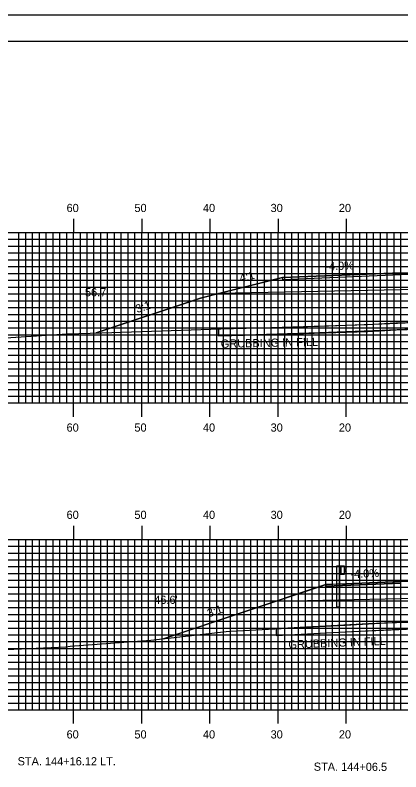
# Model space of a CAD drawing. Extents: x 1777138 to 1777481, y 442591 to 442811.
# Drawn here: x 1777235.2 to 1777291.8, y 442699.6 to 442810.5 of the extents above; entities that cross this region are included whole.
import ezdxf

# ---------------------------------------------------------------- set-up
doc = ezdxf.new("R2010")
doc.units = 0
for name, color, linetype in [('ANNOTATION', 7, 'Continuous'), ('BORDER', 7, 'Continuous'), ('BORING - NO REFUSAL', 7, 'Continuous'), ('D_Guardrail_Beam_Lt', 7, 'Continuous'), ('D_Roadway_Centerline', 7, 'Continuous'), ('D_Roadway_Edge_Shoulder', 7, 'Continuous'), ('D_Roadway_SlopeLines', 7, 'Continuous'), ('D_Roadway_SubGrade', 7, 'Continuous'), ('D_Text_Standard', 7, 'Continuous'), ('GRUBBING IN FILL', 7, 'Continuous'), ('H_V ANNOTATION', 7, 'Continuous'), ('MAJOR', 7, 'Continuous'), ('MINOR', 7, 'Continuous'), ('PLOT BOUNDARY', 7, 'Continuous'), ('S_Roadway_Centerline', 7, 'Continuous')]:
    doc.layers.add(name, color=color, linetype=linetype)

msp = doc.modelspace()

# ---------------------------------------------------------------- linework, layer by layer
at = {"layer": 'BORDER'}
msp.add_lwpolyline([(1777154.16, 442596.67), (1777474.16, 442596.67), (1777474.16, 442806.67), (1777154.16, 442806.67)], close=True, dxfattribs=at)
at = {"layer": 'D_Guardrail_Beam_Lt'}
for p, q in [((1777282.33, 442729.74), (1777282.33, 442723.74)), ((1777282.81, 442729.74), (1777282.33, 442729.74)), ((1777283.49, 442729.74), (1777282.81, 442729.74)), ((1777282.81, 442729.74), (1777282.81, 442728.57)), ((1777282.87, 442729.74), (1777282.87, 442728.57)), ((1777282.97, 442729.74), (1777282.97, 442728.57)), ((1777283.49, 442728.57), (1777283.49, 442729.74)), ((1777283.49, 442729.66), (1777283.57, 442729.64)), ((1777283.58, 442729.64), (1777283.73, 442729.54)), ((1777282.81, 442728.57), (1777283.49, 442728.57)), ((1777282.83, 442723.74), (1777282.83, 442728.57)), ((1777283.57, 442728.67), (1777283.49, 442728.66)), ((1777283.5, 442729.19), (1777283.5, 442729.12)), ((1777283.73, 442729.39), (1777283.53, 442729.26)), ((1777283.53, 442729.06), (1777283.73, 442728.92)), ((1777283.73, 442728.78), (1777283.58, 442728.68)), ((1777282.83, 442723.74), (1777282.33, 442723.74))]:
    msp.add_line(p, q, dxfattribs=at)
for centre, major_axis, start_param, end_param in [((1777283.56, 442729.6), (0.0417, 0), 0.959931, 1.376053), ((1777283.58, 442729.19), (-0.0789, 0), 5.323254, 6.283185), ((1777283.58, 442729.12), (-0.0789, 0), 6.283185, 7.243116), ((1777283.56, 442728.71), (0.0417, 0), 4.907132, 5.323254), ((1777283.68, 442729.46), (0.0877, 0), 5.323254, 7.243116), ((1777283.68, 442728.85), (0.0877, 0), 5.323254, 7.243116)]:
    msp.add_ellipse(centre, major_axis=major_axis, ratio=0.995501, start_param=start_param, end_param=end_param, dxfattribs=at)
at = {"layer": 'D_Roadway_Centerline'}
for points in [[(1777247.09, 442763.95), (1777262.4, 442769.05), (1777262.91, 442769.17), (1777265.04, 442769.71), (1777265.04, 442769.71), (1777274.4, 442772.05), (1777274.4, 442772.05), (1777291.75, 442772.74), (1777291.76, 442772.74), (1777303.76, 442772.98), (1777303.76, 442772.98), (1777306.36, 442772.93), (1777315.76, 442772.74), (1777315.76, 442772.74), (1777315.77, 442772.74), (1777323.76, 442772.42), (1777323.77, 442772.42), (1777333.94, 442769.88), (1777345.32, 442767.03), (1777345.32, 442767.03)], [(1777256.93, 442719.09), (1777257.05, 442719.13), (1777263.52, 442721.29), (1777273.48, 442724.61), (1777273.49, 442724.61), (1777279.92, 442726.76), (1777280.75, 442727.03), (1777280.76, 442727.04), (1777281.76, 442727.08), (1777283.76, 442727.16), (1777291.76, 442727.48), (1777291.76, 442727.48), (1777291.77, 442727.48), (1777296.04, 442727.56), (1777303.76, 442727.72), (1777314.18, 442727.51), (1777315.76, 442727.48), (1777323.76, 442727.16), (1777333.94, 442724.61), (1777335.76, 442724.16), (1777342.08, 442722.58), (1777342.13, 442722.57)]]:
    msp.add_lwpolyline(points, dxfattribs=at)
at = {"layer": 'D_Roadway_Edge_Shoulder'}
for points in [[(1777291.76, 442772.74), (1777274.4, 442772.05), (1777274.4, 442771.8), (1777291.76, 442772.49)], [(1777291.76, 442727.48), (1777283.76, 442727.16), (1777283.76, 442727.16), (1777280.76, 442727.04), (1777280.76, 442726.79), (1777291.76, 442727.23)]]:
    msp.add_lwpolyline(points, close=True, dxfattribs=at)
at = {"layer": 'D_Roadway_SlopeLines'}
for points in [[(1777274.4, 442772.05), (1777262.4, 442769.05), (1777247.09, 442763.95)], [(1777280.76, 442727.04), (1777256.93, 442719.09)]]:
    msp.add_lwpolyline(points, dxfattribs=at)
at = {"layer": 'D_Roadway_SubGrade'}
for points in [[(1777291.76, 442770.24), (1777265.04, 442769.71), (1777274.4, 442772.05), (1777274.4, 442771.8), (1777291.76, 442772.49), (1777303.76, 442772.73), (1777315.76, 442772.49), (1777323.76, 442772.17), (1777323.76, 442772.42), (1777333.94, 442769.88), (1777315.76, 442770.24), (1777303.76, 442770.48)], [(1777291.76, 442726.81), (1777291.76, 442727.23), (1777280.76, 442726.79), (1777280.76, 442727.04), (1777273.49, 442724.61), (1777291.76, 442724.98)]]:
    msp.add_lwpolyline(points, close=True, dxfattribs=at)
at = {"layer": 'GRUBBING IN FILL'}
msp.add_line((1777265.04, 442764.54), (1777265.04, 442763.54), dxfattribs=at)
msp.add_line((1777265.04, 442764.54), (1777265.04, 442763.54), dxfattribs=at)
for points in [[(1777265.04, 442764.54), (1777272.78, 442764.73), (1777279.81, 442764.95), (1777288.95, 442765.28), (1777295.88, 442765.56), (1777303.76, 442765.63), (1777303.76, 442764.63), (1777299.87, 442764.59), (1777293.49, 442764.48), (1777288.99, 442764.29), (1777279.85, 442763.95), (1777268.92, 442763.63), (1777265.04, 442763.54)], [(1777265.04, 442764.54), (1777272.78, 442764.73), (1777279.81, 442764.95), (1777288.95, 442765.28), (1777295.88, 442765.56), (1777303.76, 442765.63), (1777303.76, 442764.63), (1777299.87, 442764.59), (1777293.49, 442764.48), (1777288.99, 442764.29), (1777279.85, 442763.95), (1777268.92, 442763.63), (1777265.04, 442763.54)], [(1777273.49, 442719.58), (1777283.6, 442720.11), (1777293.7, 442720.55), (1777303.76, 442720.77), (1777303.76, 442721.77), (1777296.24, 442721.61), (1777292.81, 442721.53), (1777287.03, 442721.29), (1777275.17, 442720.67), (1777273.49, 442720.58)], [(1777273.49, 442719.58), (1777283.6, 442720.11), (1777293.7, 442720.55), (1777303.76, 442720.77), (1777303.76, 442721.77), (1777296.24, 442721.61), (1777292.81, 442721.53), (1777287.03, 442721.29), (1777275.17, 442720.67), (1777273.49, 442720.58)]]:
    msp.add_lwpolyline(points, close=True, dxfattribs=at)
for points in [[(1777265.04, 442763.54), (1777272.8, 442763.73), (1777286.9, 442764.17), (1777291.09, 442764.4), (1777295.9, 442764.56), (1777303.85, 442764.63), (1777310.79, 442765.28), (1777315.98, 442765.62), (1777333.94, 442765.48)], [(1777265.04, 442763.54), (1777272.8, 442763.73), (1777286.9, 442764.17), (1777291.09, 442764.4), (1777295.9, 442764.56), (1777303.85, 442764.63), (1777310.79, 442765.28), (1777315.98, 442765.62), (1777333.94, 442765.48)], [(1777273.49, 442724.61), (1777291.76, 442724.98), (1777303.76, 442725.22), (1777315.76, 442724.98), (1777333.94, 442724.61)], [(1777273.49, 442724.61), (1777291.76, 442724.98), (1777303.76, 442725.22), (1777315.76, 442724.98), (1777333.94, 442724.61)], [(1777273.49, 442719.58), (1777283.6, 442720.11), (1777290.55, 442720.47), (1777291.14, 442720.49), (1777296.26, 442720.61), (1777312.37, 442720.95), (1777314.06, 442721), (1777325.45, 442721.39), (1777333.94, 442721.39)], [(1777273.49, 442719.58), (1777283.6, 442720.11), (1777290.55, 442720.47), (1777291.14, 442720.49), (1777296.26, 442720.61), (1777312.37, 442720.95), (1777314.06, 442721), (1777325.45, 442721.39), (1777333.94, 442721.39)]]:
    msp.add_lwpolyline(points, dxfattribs=at)
at = {"layer": 'MAJOR'}
for p, q in [((1777243.76, 442780.67), (1777243.76, 442778.67)), ((1777253.76, 442780.67), (1777253.76, 442778.67)), ((1777263.76, 442780.67), (1777263.76, 442778.67)), ((1777273.76, 442780.67), (1777273.76, 442778.67)), ((1777283.76, 442780.67), (1777283.76, 442778.67)), ((1777163.76, 442778.67), (1777443.76, 442778.67)), ((1777163.76, 442778.67), (1777443.76, 442778.67)), ((1777243.76, 442753.67), (1777243.76, 442778.67)), ((1777253.76, 442753.67), (1777253.76, 442778.67)), ((1777263.76, 442753.67), (1777263.76, 442778.67)), ((1777273.76, 442753.67), (1777273.76, 442778.67)), ((1777283.76, 442753.67), (1777283.76, 442778.67)), ((1777163.76, 442773.67), (1777443.76, 442773.67)), ((1777163.76, 442768.67), (1777443.76, 442768.67)), ((1777163.76, 442763.67), (1777443.76, 442763.67)), ((1777163.76, 442758.67), (1777443.76, 442758.67)), ((1777163.76, 442753.67), (1777443.76, 442753.67)), ((1777163.76, 442753.67), (1777443.76, 442753.67)), ((1777243.76, 442751.66), (1777243.76, 442753.67)), ((1777253.76, 442751.66), (1777253.76, 442753.67)), ((1777263.76, 442751.66), (1777263.76, 442753.67)), ((1777273.76, 442751.66), (1777273.76, 442753.67)), ((1777283.76, 442751.66), (1777283.76, 442753.67)), ((1777243.76, 442735.67), (1777243.76, 442733.67)), ((1777253.76, 442735.67), (1777253.76, 442733.67)), ((1777263.76, 442735.67), (1777263.76, 442733.67)), ((1777273.76, 442735.67), (1777273.76, 442733.67)), ((1777283.76, 442735.67), (1777283.76, 442733.67)), ((1777163.76, 442733.67), (1777443.76, 442733.67)), ((1777163.76, 442733.67), (1777443.76, 442733.67)), ((1777243.76, 442708.67), (1777243.76, 442733.67)), ((1777253.76, 442708.67), (1777253.76, 442733.67)), ((1777263.76, 442708.67), (1777263.76, 442733.67)), ((1777273.76, 442708.67), (1777273.76, 442733.67)), ((1777283.76, 442708.67), (1777283.76, 442733.67)), ((1777163.76, 442728.67), (1777443.76, 442728.67)), ((1777163.76, 442723.67), (1777443.76, 442723.67)), ((1777163.76, 442718.67), (1777443.76, 442718.67)), ((1777163.76, 442713.67), (1777443.76, 442713.67)), ((1777163.76, 442708.67), (1777443.76, 442708.67)), ((1777163.76, 442708.67), (1777443.76, 442708.67)), ((1777243.76, 442706.66), (1777243.76, 442708.67)), ((1777253.76, 442706.66), (1777253.76, 442708.67)), ((1777263.76, 442706.66), (1777263.76, 442708.67)), ((1777273.76, 442706.66), (1777273.76, 442708.67)), ((1777283.76, 442706.66), (1777283.76, 442708.67))]:
    msp.add_line(p, q, dxfattribs=at)
at = {"layer": 'MINOR'}
for p, q in [((1777235.76, 442753.67), (1777235.76, 442778.67)), ((1777236.76, 442753.67), (1777236.76, 442778.67)), ((1777237.76, 442753.67), (1777237.76, 442778.67)), ((1777238.76, 442753.67), (1777238.76, 442778.67)), ((1777239.76, 442753.67), (1777239.76, 442778.67)), ((1777240.76, 442753.67), (1777240.76, 442778.67)), ((1777241.76, 442753.67), (1777241.76, 442778.67)), ((1777242.76, 442753.67), (1777242.76, 442778.67)), ((1777244.76, 442753.67), (1777244.76, 442778.67)), ((1777245.76, 442753.67), (1777245.76, 442778.67)), ((1777246.76, 442753.67), (1777246.76, 442778.67)), ((1777247.76, 442753.67), (1777247.76, 442778.67)), ((1777248.76, 442753.67), (1777248.76, 442778.67)), ((1777249.76, 442753.67), (1777249.76, 442778.67)), ((1777250.76, 442753.67), (1777250.76, 442778.67)), ((1777251.76, 442753.67), (1777251.76, 442778.67)), ((1777252.76, 442753.67), (1777252.76, 442778.67)), ((1777254.76, 442753.67), (1777254.76, 442778.67)), ((1777255.76, 442753.67), (1777255.76, 442778.67)), ((1777256.76, 442753.67), (1777256.76, 442778.67)), ((1777257.76, 442753.67), (1777257.76, 442778.67)), ((1777258.76, 442753.67), (1777258.76, 442778.67)), ((1777259.76, 442753.67), (1777259.76, 442778.67)), ((1777260.76, 442753.67), (1777260.76, 442778.67)), ((1777261.76, 442753.67), (1777261.76, 442778.67)), ((1777262.76, 442753.67), (1777262.76, 442778.67)), ((1777264.76, 442753.67), (1777264.76, 442778.67)), ((1777265.76, 442753.67), (1777265.76, 442778.67)), ((1777266.76, 442753.67), (1777266.76, 442778.67)), ((1777267.76, 442753.67), (1777267.76, 442778.67)), ((1777268.76, 442753.67), (1777268.76, 442778.67)), ((1777269.76, 442753.67), (1777269.76, 442778.67)), ((1777270.76, 442753.67), (1777270.76, 442778.67)), ((1777271.76, 442753.67), (1777271.76, 442778.67)), ((1777272.76, 442753.67), (1777272.76, 442778.67)), ((1777274.76, 442753.67), (1777274.76, 442778.67)), ((1777275.76, 442753.67), (1777275.76, 442778.67)), ((1777276.76, 442753.67), (1777276.76, 442778.67)), ((1777277.76, 442753.67), (1777277.76, 442778.67)), ((1777278.76, 442753.67), (1777278.76, 442778.67)), ((1777279.76, 442753.67), (1777279.76, 442778.67)), ((1777280.76, 442753.67), (1777280.76, 442778.67)), ((1777281.76, 442753.67), (1777281.76, 442778.67)), ((1777282.76, 442753.67), (1777282.76, 442778.67)), ((1777284.76, 442753.67), (1777284.76, 442778.67)), ((1777285.76, 442753.67), (1777285.76, 442778.67)), ((1777286.76, 442753.67), (1777286.76, 442778.67)), ((1777287.76, 442753.67), (1777287.76, 442778.67)), ((1777288.76, 442753.67), (1777288.76, 442778.67)), ((1777289.76, 442753.67), (1777289.76, 442778.67)), ((1777290.76, 442753.67), (1777290.76, 442778.67)), ((1777291.76, 442753.67), (1777291.76, 442778.67)), ((1777163.76, 442777.67), (1777443.76, 442777.67)), ((1777163.76, 442776.67), (1777443.76, 442776.67)), ((1777163.76, 442775.67), (1777443.76, 442775.67)), ((1777163.76, 442774.67), (1777443.76, 442774.67)), ((1777163.76, 442772.67), (1777443.76, 442772.67)), ((1777163.76, 442771.67), (1777443.76, 442771.67)), ((1777163.76, 442770.67), (1777443.76, 442770.67)), ((1777163.76, 442769.67), (1777443.76, 442769.67)), ((1777163.76, 442767.67), (1777443.76, 442767.67)), ((1777163.76, 442766.67), (1777443.76, 442766.67)), ((1777163.76, 442765.67), (1777443.76, 442765.67)), ((1777163.76, 442764.67), (1777443.76, 442764.67)), ((1777163.76, 442762.67), (1777443.76, 442762.67)), ((1777163.76, 442761.67), (1777443.76, 442761.67)), ((1777163.76, 442760.67), (1777443.76, 442760.67)), ((1777163.76, 442759.67), (1777443.76, 442759.67)), ((1777163.76, 442757.67), (1777443.76, 442757.67)), ((1777163.76, 442756.67), (1777443.76, 442756.67)), ((1777163.76, 442755.67), (1777443.76, 442755.67)), ((1777163.76, 442754.67), (1777443.76, 442754.67)), ((1777235.76, 442708.67), (1777235.76, 442733.67)), ((1777236.76, 442708.67), (1777236.76, 442733.67)), ((1777237.76, 442708.67), (1777237.76, 442733.67)), ((1777238.76, 442708.67), (1777238.76, 442733.67)), ((1777239.76, 442708.67), (1777239.76, 442733.67)), ((1777240.76, 442708.67), (1777240.76, 442733.67)), ((1777241.76, 442708.67), (1777241.76, 442733.67)), ((1777242.76, 442708.67), (1777242.76, 442733.67)), ((1777244.76, 442708.67), (1777244.76, 442733.67)), ((1777245.76, 442708.67), (1777245.76, 442733.67)), ((1777246.76, 442708.67), (1777246.76, 442733.67)), ((1777247.76, 442708.67), (1777247.76, 442733.67)), ((1777248.76, 442708.67), (1777248.76, 442733.67)), ((1777249.76, 442708.67), (1777249.76, 442733.67)), ((1777250.76, 442708.67), (1777250.76, 442733.67)), ((1777251.76, 442708.67), (1777251.76, 442733.67)), ((1777252.76, 442708.67), (1777252.76, 442733.67)), ((1777254.76, 442708.67), (1777254.76, 442733.67)), ((1777255.76, 442708.67), (1777255.76, 442733.67)), ((1777256.76, 442708.67), (1777256.76, 442733.67)), ((1777257.76, 442708.67), (1777257.76, 442733.67)), ((1777258.76, 442708.67), (1777258.76, 442733.67)), ((1777259.76, 442708.67), (1777259.76, 442733.67)), ((1777260.76, 442708.67), (1777260.76, 442733.67)), ((1777261.76, 442708.67), (1777261.76, 442733.67)), ((1777262.76, 442708.67), (1777262.76, 442733.67)), ((1777264.76, 442708.67), (1777264.76, 442733.67)), ((1777265.76, 442708.67), (1777265.76, 442733.67)), ((1777266.76, 442708.67), (1777266.76, 442733.67)), ((1777267.76, 442708.67), (1777267.76, 442733.67)), ((1777268.76, 442708.67), (1777268.76, 442733.67)), ((1777269.76, 442708.67), (1777269.76, 442733.67)), ((1777270.76, 442708.67), (1777270.76, 442733.67)), ((1777271.76, 442708.67), (1777271.76, 442733.67)), ((1777272.76, 442708.67), (1777272.76, 442733.67)), ((1777274.76, 442708.67), (1777274.76, 442733.67)), ((1777275.76, 442708.67), (1777275.76, 442733.67)), ((1777276.76, 442708.67), (1777276.76, 442733.67)), ((1777277.76, 442708.67), (1777277.76, 442733.67)), ((1777278.76, 442708.67), (1777278.76, 442733.67)), ((1777279.76, 442708.67), (1777279.76, 442733.67)), ((1777280.76, 442708.67), (1777280.76, 442733.67)), ((1777281.76, 442708.67), (1777281.76, 442733.67)), ((1777282.76, 442708.67), (1777282.76, 442733.67)), ((1777284.76, 442708.67), (1777284.76, 442733.67)), ((1777285.76, 442708.67), (1777285.76, 442733.67)), ((1777286.76, 442708.67), (1777286.76, 442733.67)), ((1777287.76, 442708.67), (1777287.76, 442733.67)), ((1777288.76, 442708.67), (1777288.76, 442733.67)), ((1777289.76, 442708.67), (1777289.76, 442733.67)), ((1777290.76, 442708.67), (1777290.76, 442733.67)), ((1777291.76, 442708.67), (1777291.76, 442733.67)), ((1777163.76, 442732.67), (1777443.76, 442732.67)), ((1777163.76, 442731.67), (1777443.76, 442731.67)), ((1777163.76, 442730.67), (1777443.76, 442730.67)), ((1777163.76, 442729.67), (1777443.76, 442729.67)), ((1777163.76, 442727.67), (1777443.76, 442727.67)), ((1777163.76, 442726.67), (1777443.76, 442726.67)), ((1777163.76, 442725.67), (1777443.76, 442725.67)), ((1777163.76, 442724.67), (1777443.76, 442724.67)), ((1777163.76, 442722.67), (1777443.76, 442722.67)), ((1777163.76, 442721.67), (1777443.76, 442721.67)), ((1777163.76, 442720.67), (1777443.76, 442720.67)), ((1777163.76, 442719.67), (1777443.76, 442719.67)), ((1777163.76, 442717.67), (1777443.76, 442717.67)), ((1777163.76, 442716.67), (1777443.76, 442716.67)), ((1777163.76, 442715.67), (1777443.76, 442715.67)), ((1777163.76, 442714.67), (1777443.76, 442714.67)), ((1777163.76, 442712.67), (1777443.76, 442712.67)), ((1777163.76, 442711.67), (1777443.76, 442711.67)), ((1777163.76, 442710.67), (1777443.76, 442710.67)), ((1777163.76, 442709.67), (1777443.76, 442709.67))]:
    msp.add_line(p, q, dxfattribs=at)
at = {"layer": 'PLOT BOUNDARY'}
msp.add_lwpolyline([(1777137.98, 442590.55), (1777477.98, 442590.55), (1777477.98, 442810.55), (1777137.98, 442810.55)], close=True, dxfattribs=at)
at = {"layer": 'S_Roadway_Centerline'}
for points in [[(1777233.05, 442763.19), (1777242.81, 442763.82), (1777247.92, 442763.97), (1777265.37, 442764.55), (1777272.78, 442764.73), (1777286.85, 442765.17), (1777291.05, 442765.4), (1777295.88, 442765.56), (1777303.8, 442765.63), (1777310.71, 442766.28), (1777315.95, 442766.62), (1777332.71, 442766.49), (1777337.23, 442766.64), (1777342.58, 442766.86), (1777350.1, 442767.34), (1777356.27, 442767.47), (1777367.15, 442767.83)], [(1777223.02, 442717.02), (1777242.61, 442717.93), (1777243.25, 442718), (1777255.11, 442718.88), (1777266.16, 442720.18), (1777266.8, 442720.23), (1777283.55, 442721.11), (1777290.51, 442721.46), (1777291.11, 442721.49), (1777296.24, 442721.61), (1777312.34, 442721.95), (1777314.03, 442722), (1777325.43, 442722.39), (1777334.97, 442722.39), (1777339.88, 442722.5), (1777348.82, 442722.76), (1777359.02, 442723.53), (1777361.9, 442723.61)]]:
    msp.add_lwpolyline(points, dxfattribs=at)

# ---------------------------------------------------------------- texts
at = {"layer": 'ANNOTATION'}
for s, rotation, p in [('-4.0%', 2.2927, (1777280.71, 442773.1)), ('4:1', 14.0356, (1777268.26, 442771.37)), ('3:1', 18.4328, (1777253.09, 442766.85)), ('-4.0%', 2.2906, (1777284.39, 442727.98)), ('3:1', 18.4349, (1777263.6, 442722.23))]:
    msp.add_text(s, height=1.2, rotation=rotation, dxfattribs=at).set_placement(p)
at = {"layer": 'BORING - NO REFUSAL'}
msp.add_text('STA. 144+06.5', height=1.2, rotation=359.8142, dxfattribs=at).set_placement((1777278.99, 442699.74))
at = {"layer": 'D_Text_Standard'}
for s, p in [("56.7'", (1777245.44, 442769.32)), ("46.6'", (1777255.6, 442724.21)), ('STA. 144+16.12 LT.', (1777235.56, 442700.53))]:
    msp.add_text(s, height=1.2, dxfattribs=at).set_placement(p)
at = {"layer": 'GRUBBING IN FILL'}
for rotation, p in [(1.122, (1777265.37, 442761.76)), (2.2667, (1777275.3, 442717.63))]:
    msp.add_text('GRUBBING IN FILL', height=1.2, rotation=rotation, dxfattribs=at).set_placement(p)
at = {"layer": 'H_V ANNOTATION'}
for s, p in [('60', (1777242.74, 442781.67)), ('50', (1777252.69, 442781.67)), ('40', (1777262.74, 442781.67)), ('30', (1777272.66, 442781.67)), ('20', (1777282.67, 442781.67)), ('60', (1777242.74, 442749.47)), ('50', (1777252.69, 442749.47)), ('40', (1777262.74, 442749.47)), ('30', (1777272.66, 442749.47)), ('20', (1777282.67, 442749.47)), ('60', (1777242.74, 442736.67)), ('50', (1777252.69, 442736.67)), ('40', (1777262.74, 442736.67)), ('30', (1777272.66, 442736.67)), ('20', (1777282.67, 442736.67)), ('60', (1777242.74, 442704.47)), ('50', (1777252.69, 442704.47)), ('40', (1777262.74, 442704.47)), ('30', (1777272.66, 442704.47)), ('20', (1777282.67, 442704.47))]:
    msp.add_text(s, height=1.2, dxfattribs=at).set_placement(p)

doc.saveas('drawing.dxf')
